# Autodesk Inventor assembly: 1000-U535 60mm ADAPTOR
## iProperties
Created: 2007-03
Part Number: 1000-U535 60mm ADAPTOR
Document SubType Name: Assembly
Designer: Andy Moles
Translation Standard: STEP AP214IS
File Name: 1000-U535_ASM
Preprocessor: PRO/ENGINEER BY PARAMETRIC TECHNOLOGY CORPORATION, 2003200
Postprocessor: Build: 344b, Release: 11 SP2 - Date: Fri 08/18/2006
Sent Units: MILLIMETERS
Uncertainty: 0.005974347976660001
Author: Andy Moles
